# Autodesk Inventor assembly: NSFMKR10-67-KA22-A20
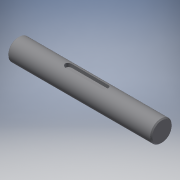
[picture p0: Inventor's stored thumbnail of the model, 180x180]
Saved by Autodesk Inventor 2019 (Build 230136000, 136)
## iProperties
Category: PARTsolutions
Company: MISUMI
Created: 2022-11
Part Number: NSFMKR10-67-KA22-A20
Catalog Web Link: www.cadenas.de
Description: NSFMKR, SFMKR, PSFMKR, SSFMKR, NSFHKR, SFHKR, PSFHKR, SSFHKR, NSFGKR, SFGKR, PSFGKR, SSFGKR-Rotary Shafts - Straight with Keyway -
Vendor: MISUMI
Document SubType Name: Assembly
Designer: psAdmin
Manufacturer: MISUMI
Mass: 5.15435 g
Surface Area: 23.1132 cm^2
Volume: 5.15435 cm^3
Density: 1 g/cm^3
Title: NSFMKR10-67-KA22-A20
Author: Cadenas PARTsolutions
Comments: Rotary Shafts - Straight with Keyway -
PSOL_IDENT_0: {$CADENAS_DATA/23d-libs/misumi/metric/11_rotary_shafts/psfgkr_asmtab.prj},488 {VTYP=3D},{STYP=ASSTAB
PSOL_IDENT_1: },{NB=NSFMKR10-67-KA22-A20},{LINA=NSFMKR10-67-KA22-A20},{NN=NSFMKR, SFMKR, PSFMKR, SSFMKR, NSFHKR, S
PSOL_IDENT_2: FHKR, PSFHKR, SSFHKR, NSFGKR, SFGKR, PSFGKR, SSFGKR},{DATE=25.01.2022 23:09:58},{GEOMDATE=05.02.2021
PSOL_IDENT_3: 08:01:18},{VERSION=},{LINEID=30},{WBVAR=TS,MAT,ST,ALT1,L,NOK,KA,A,KB,B,KC,C,ALT3,FC,GALT3,WFC,J,WAL
PSOL_IDENT_4: T3,V,ALT4,SFC,SGALT4,AG,ALT10,KWC,ALT11,WC,ALT6,TA,TB,ALT5,UC,ALT7,SC,ALT32,CD},{WBNUMERIC=L,KA,A,KB
PSOL_IDENT_5: ,B,KC,C,FC,GALT3,WFC,J,WALT3,V,SFC,SGALT4,AG,KWC,WC,TA,TB,UC,SC}  {NB=NSFMKR10-67-KA22-A20},{LINA=NS
PSOL_IDENT_6: FMKR10-67-KA22-A20},{KT=DUMMY},{PN=NSFMKR10-67-KA22-A20},{TS=M},{TSALG= 'M','h9 (Cold-drawn)','H','h
PSOL_IDENT_7: 7 (Ground)','G','g6 (Ground)' },{MAT=S45C},{MATALG= 'S45C','S45C Equivalent', 'SUS304','SUS304' },{S
PSOL_IDENT_8: T=},{STALG= '','-','BO','Black Oxide', 'ENP','Electroless Nickel Plating' },{TYPE=NSFMKR},{D=10},{AL
PSOL_IDENT_9: T1=},{L=67.0},{LALG=[15:800/0.1]},{LMIN=15},{LMAX=800},{NOK=1},{NOKALG= '1', 'with 1 Key Groove', '2'
PSOL_IDENT_10: , 'with 2 Key Grooves', '3'  , 'with 3 Key Grooves'},{BB=3},{TT=1.8},{KA=22.0},{KAALG=[0:64/0.1]},
PSOL_IDENT_11: {KAMIN=0},{KAMAX1=64},{KAMAX2=59},{KAMAX3=54},{A=20.0},{AALG=[3:45/0.1]},{AMIN=3},{AMAX1=45},{AMAX2=
PSOL_IDENT_12: 40},{AMAX3=35},{KAPN=-KA22-A20},{KB=0.0},{KBALG=[0]},{KBMIN=44},{KBMAX1=64},{KBMAX2=59},{B=0.0},{BAL
PSOL_IDENT_13: G=[0]},{BMIN=3},{BMAX1=67},{BMAX2=62},{KBPN=},{KC=0.0},{KCALG=[0]},{KCMIN=2},{KCMAX=64},{C=0.0},{CAL
PSOL_IDENT_14: G=[0]},{CMIN=3},{CMAX=67},{KCPN=},{CIFKA=5},{CIFKB=3},{CIFKC=3},{ALT3=},{ALT3ALG= '', 'w/o Set Screw
PSOL_IDENT_15: Flat','FC','with FC (Adds a Set Screw Flat)','WFC','with WFC (Adds Two Set Screw Flats)','FCWFC','w
PSOL_IDENT_16: ith FC + WFC (Adds Three Set Screw Flats)' },{ALT3PN=},{FC=0},{FCALG=[0]},{FCMIN=0},{FCMAX=66},{GALT
PSOL_IDENT_17: 3=0},{GALT3ALG=[0]},{GALT3MIN=1},{GALT3MAX=67},{GALT3MAX2=61},{GALT3MAX3=64},{WFC=0},{WFCALG=[0]},{W
PSOL_IDENT_18: FCMIN=0},{WFCMIN2=2},{WFCMAX=63},{WFCMAX2=-3},{WFCMAX3=-4},{J=0},{JALG=[0]},{JMIN=1},{JMAX=64},{JMAX
PSOL_IDENT_19: 2=-2},{JMAX3=-5},{WALT3=0},{WALT3ALG=[0]},{WALT3MIN=0},{WALT3MIN2=69},{WALT3MAX=64},{WALT3MAX2=64},{
PSOL_IDENT_20: V=0},{VALG=[0]},{VMIN=1},{VMAX=65},{VMAX3=65},{CIFFC=0},{ALT4=},{ALT4ALG= '', 'w/o SFC (2 Set Screw
PSOL_IDENT_21: Flats (Angle Specified))', 'SFC' , 'with SFC (2 Set Screw Flats (Angle Specified))'},{ALT4PN=},{SFC=
PSOL_IDENT_22: 0},{SFCALG=[0]},{SFCMIN=0},{SFCMAX=66},{SGALT4=0},{SGALT4ALG=[0]},{SGALT4MIN=1},{SGALT4MAX=50},{AG=0
PSOL_IDENT_23: },{AGALG=[0]},{H=0},{CIFSFC=0},{ALT10=},{ALT10ALG= '', 'w/o KWC (2 Set Screw Flats at both ends)', '
PSOL_IDENT_24: KWC', 'with KWC (2 Set Screw Flats at both ends)' },{ALT10PN=},{KWC=0},{KWCALG=[0]},{KWCMIN=1},{KWCM
PSOL_IDENT_25: AX=32.5},{WALT10=8},{ALT11=},{ALT11ALG= '','Not applicable' },{ALT11PN=},{WC=0.0},{WCALG=[0]},{ALT6=
PSOL_IDENT_26: },{ALT6ALG= '','w/o Retaining Ring Groove','TA','with TA (Retaining Ring Groove)','TB','with TB (Ret
PSOL_IDENT_27: aining Ring Groove)','TATB','with TA + TB (Two Retaining Ring Grooves)' },{ALT6PN=},{TA=0.0},{TAALG=
PSOL_IDENT_28: [0]},{TAMIN=2},{TAMAX=0},{TB=0.0},{TBALG=[0]},{TBMIN=2},{TBMAX=0},{DDALT6=0.0},{MM=0.00},{ALT5=},{AL
PSOL_IDENT_29: T5ALG= '', 'w/o UC (Slit Cam Groove)', 'UC', 'with UC (Slit Cam Groove)'},{ALT5PN=},{UC=0},{UCALG=[0
PSOL_IDENT_30: ]},{UCMIN=1},{UCMAX=61},{DD=0},{LL1=0},{ALT7=},{ALT7ALG= '', 'w/o SC (Wrench Flats)', 'SC', 'with SC
PSOL_IDENT_31: (Wrench Flats)'},{ALT7PN=},{SC=0},{SCALG=[0]},{SCMIN=0},{SCMAX=59},{WALT7=0},{LL2=0},{LL2ALG=8},{CI
PSOL_IDENT_32: FSC=0},{ALT32=},{ALT32ALG=  '','w/o CD (Changes Part D Chamfering)','CD', 'with CD (Changes Part D C
PSOL_IDENT_33: hamfering)' },{ALT32PN=},{CD=},{CDALG= '','' },{CD3D=0.5},{CIF32=0},{CIF320=0},{CIF32FC=0},{CIF32WFC=
PSOL_IDENT_34: 0},{CIF32WALT3=0},{ERRORPN=},{ERRORKGALT3=OK},{ERRORKGALT4=OK},{ERRORKGALT5=OK},{ERRORKGALT7=OK},{ER
PSOL_IDENT_35: RORKGALT10=OK},{ERRORALT34=OK},{ERRORALT35=OK},{ERRORALT37=OK},{ERRORALT310=OK},{ERRORALT45=OK},{ERR
PSOL_IDENT_36: ORALT47=OK},{ERRORALT410=OK},{ERRORALT57=OK},{ERRORALT510=OK},{ERRORALT710=OK},{ERRORALT36=OK},{ERRO
PSOL_IDENT_37: RALT46=OK},{ERRORALT56=OK},{ERRORALT67=OK},{ERRORALT610=OK},{ERRORKGALT6=OK},{CIFTA=0},{CIFTB=0},{PP
PSOL_IDENT_38: ATH=11_components/psfgkr/psfgkr_asmtpl.prj}
NB: NSFMKR10-67-KA22-A20
NN: NSFMKR, SFMKR, PSFMKR, SSFMKR, NSFHKR, SFHKR, PSFHKR, SSFHKR, NSFGKR, SFGKR, PSFGKR, SSFGKR
NT: Rotary Shafts - Straight with Keyway -
NBSYN: $PN.
LINA: NSFMKR10-67-KA22-A20
CATALOG: Misumi
PN: NSFMKR10-67-KA22-A20
TS: h9 (Cold-drawn)
MAT: S45C Equivalent
ST: -
D: 10
ALT1: w/o LKC (Changes L Tolerance)
L: 67
NOK: with 1 Key Groove
KA: 22
A: 20
KB: 0
B: 0
KC: 0
C: 0
ALT3: w/o Set Screw Flat
FC: 0
GALT3: 0
WFC: 0
J: 0
WALT3: 0
V: 0
ALT4: w/o SFC (2 Set Screw Flats (Angle Specified))
SFC: 0
SGALT4: 0
AG: 0
H: 0
ALT10: w/o KWC (2 Set Screw Flats at both ends)
KWC: 0
ALT11: Not applicable
WC: 0
ALT6: w/o Retaining Ring Groove
TA: 0
TB: 0
DDALT6: 0
MM: 0
ALT5: w/o UC (Slit Cam Groove)
UC: 0
DD: 0
LL1: 0
ALT7: w/o SC (Wrench Flats)
SC: 0
WALT7: 0
LL2: 0
ALT32: w/o CD (Changes Part D Chamfering)
SUPPLIER: MISUMI
ARTICLENO: NSFMKR10-67-KA22-A20
BOMINFO: NSFMKR10-67-KA22-A20
CREATOR: CADENAS GmbH
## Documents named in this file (2)
- e:\temp\worker_COMMON_5\temp\tmp_6872_98_85c27\format_0\NSFMKR10-67-KA22-A20.iam
- e:\temp\worker_COMMON_5\temp\tmp_6872_98_85c27\format_0\NSFMKR10-67-KA22-A20_s.ipt
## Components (1 placed, 1 different names)
1. NSFMKR10-67-KA22-A20_s:1
